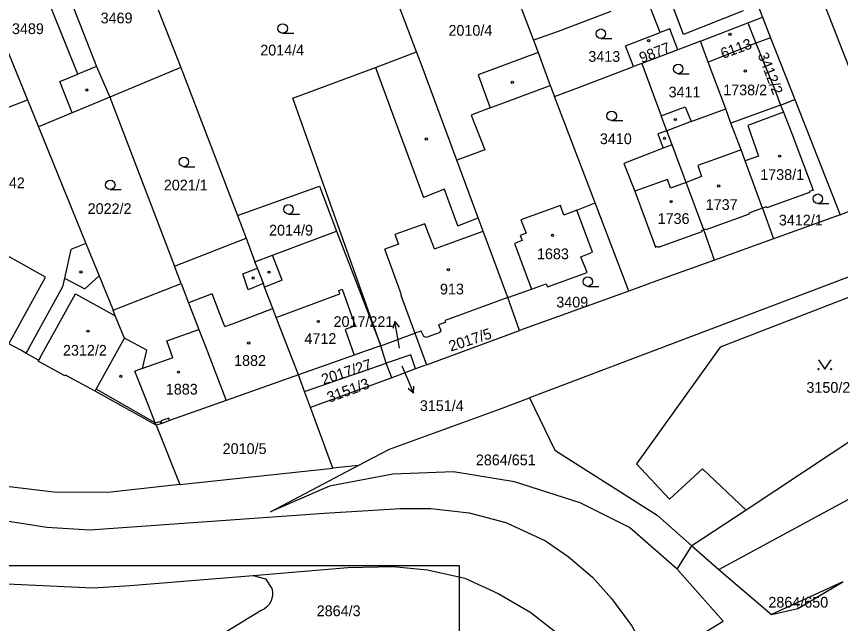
# Model space of a CAD drawing. Extents: x -564952 to -564307, y -1202373 to -1201847.
# Drawn here: x -564610.5 to -564479.9, y -1201998.2 to -1201901.9 of the extents above; entities that cross this region are included whole.
import ezdxf

# ---------------------------------------------------------------- set-up
doc = ezdxf.new("R2010")
doc.units = 0
for name, color, linetype in [('Hranice parcel', 7, 'Continuous'), ('Parcelní čísla', 7, 'Continuous'), ('Pop  PČ popisy', 7, 'Continuous'), ('Vnitřní kresba', 7, 'Continuous'), ('Vrstva 63', 7, 'Continuous'), ('Značky budov', 7, 'Continuous'), ('Značky kultur', 7, 'Continuous')]:
    doc.layers.add(name, color=color, linetype=linetype)

msp = doc.modelspace()

# ---------------------------------------------------------------- linework, layer by layer
at = {"layer": 'Hranice parcel'}
for p, q in [((-564547.1, -1201907.51), (-564552.42, -1201893.39)), ((-564495.75, -1201893.11), (-564492.24, -1201902.04)), ((-564616.36, -1201896.58), (-564608.79, -1201915.11)), ((-564531.91, -1201896.79), (-564528.57, -1201905.64)), ((-564478.1, -1201911.04), (-564483.28, -1201897.71)), ((-564508.48, -1201904.46), (-564510.58, -1201899.01)), ((-564588.08, -1201900.86), (-564584.48, -1201910.01)), ((-564516.27, -1201901.14), (-564524.64, -1201904.29)), ((-564492.24, -1201902.04), (-564491, -1201905.29)), ((-564524.64, -1201904.29), (-564528.57, -1201905.64)), ((-564513.97, -1201906.54), (-564508.48, -1201904.46)), ((-564506.95, -1201903.88), (-564508.48, -1201904.46)), ((-564505.69, -1201907.18), (-564506.95, -1201903.88)), ((-564528.57, -1201905.64), (-564527.83, -1201907.62)), ((-564502.08, -1201905.8), (-564505.69, -1201907.18)), ((-564500.85, -1201909.16), (-564502.08, -1201905.8)), ((-564491, -1201905.29), (-564493.31, -1201906.15)), ((-564491, -1201905.29), (-564487.11, -1201915.1)), ((-564512.71, -1201909.86), (-564513.97, -1201906.54)), ((-564493.31, -1201906.15), (-564500.85, -1201909.16)), ((-564493.31, -1201906.15), (-564490.23, -1201913.66)), ((-564505.69, -1201907.18), (-564511.4, -1201909.36)), ((-564511.4, -1201909.36), (-564512.71, -1201909.86)), ((-564511.4, -1201909.36), (-564508.3, -1201917.67)), ((-564498.06, -1201916.56), (-564500.85, -1201909.16)), ((-564584.48, -1201910.01), (-564595.73, -1201914.71)), ((-564584.48, -1201910.01), (-564575.5, -1201933.47)), ((-564595.73, -1201914.71), (-564601.71, -1201917.21)), ((-564595.73, -1201914.71), (-564585.46, -1201941.52)), ((-564518.79, -1201931.46), (-564525.23, -1201914.6)), ((-564490.23, -1201913.66), (-564489.4, -1201915.99)), ((-564617.51, -1201918.49), (-564608.79, -1201915.11)), ((-564608.79, -1201915.11), (-564607.03, -1201919.43)), ((-564489.4, -1201915.99), (-564497.27, -1201918.81)), ((-564489.4, -1201915.99), (-564487.11, -1201915.1)), ((-564487.11, -1201915.1), (-564479.94, -1201933.37)), ((-564601.71, -1201917.21), (-564607.03, -1201919.43)), ((-564497.27, -1201918.81), (-564498.06, -1201916.56)), ((-564507.42, -1201920.02), (-564508.3, -1201917.67)), ((-564607.03, -1201919.43), (-564599.52, -1201937.9)), ((-564492.22, -1201932.31), (-564494.98, -1201924.79)), ((-564479.94, -1201933.37), (-564470.88, -1201929.59)), ((-564513.43, -1201945.49), (-564518.79, -1201931.46)), ((-564492.22, -1201932.31), (-564490.5, -1201937.16)), ((-564575.5, -1201933.47), (-564574.13, -1201937.05)), ((-564479.94, -1201933.37), (-564490.5, -1201937.16)), ((-564499.88, -1201940.55), (-564501.55, -1201935.74)), ((-564585.46, -1201941.52), (-564574.13, -1201937.05)), ((-564574.13, -1201937.05), (-564572.71, -1201940.81)), ((-564490.5, -1201937.16), (-564499.88, -1201940.55)), ((-564599.52, -1201937.9), (-564601.88, -1201938.86)), ((-564584.42, -1201944.24), (-564585.46, -1201941.52)), ((-564595.21, -1201948.49), (-564584.42, -1201944.24)), ((-564513.43, -1201945.49), (-564530.75, -1201951.7)), ((-564530.75, -1201951.7), (-564532.64, -1201946.48)), ((-564594.85, -1201949.38), (-564595.21, -1201948.49)), ((-564449.87, -1201950.46), (-564494.86, -1201980.19)), ((-564552.78, -1201954.12), (-564547.35, -1201952.15)), ((-564547.35, -1201952.15), (-564545.5, -1201957.14)), ((-564545.5, -1201957.14), (-564530.75, -1201951.7)), ((-564551.91, -1201956.9), (-564552.78, -1201954.12)), ((-564564.86, -1201961.36), (-564551.91, -1201956.9)), ((-564551.03, -1201959.23), (-564551.91, -1201956.9)), ((-564547.25, -1201957.78), (-564551.03, -1201959.23)), ((-564545.5, -1201957.14), (-564547.25, -1201957.78)), ((-564565.82, -1201958.76), (-564577.26, -1201962.81)), ((-564564.86, -1201961.36), (-564565.82, -1201958.76)), ((-564551.03, -1201959.23), (-564563.92, -1201963.93)), ((-564499.17, -1201989.59), (-564443.23, -1201959.33)), ((-564588.36, -1201966.75), (-564598.04, -1201961.33)), ((-564563.92, -1201963.93), (-564564.86, -1201961.36)), ((-564560.38, -1201973.55), (-564563.92, -1201963.93)), ((-564588.36, -1201966.75), (-564584.64, -1201976.16)), ((-564556.34, -1201973.12), (-564551.4, -1201970.51)), ((-564584.64, -1201976.16), (-564560.38, -1201973.55)), ((-564570.25, -1201980.49), (-564556.34, -1201973.12)), ((-564556.34, -1201973.12), (-564560.38, -1201973.55)), ((-564584.64, -1201976.16), (-564596.05, -1201977.38)), ((-564494.86, -1201980.19), (-564503.43, -1201985.86)), ((-564505.77, -1201989.55), (-564503.43, -1201985.86)), ((-564503.43, -1201985.86), (-564499.17, -1201989.59)), ((-564499.17, -1201989.59), (-564490.82, -1201996.75)), ((-564479.51, -1201991.57), (-564490.82, -1201996.75))]:
    msp.add_line(p, q, dxfattribs=at)
for points in [[(-564328.21, -1201853.59), (-564368.6, -1201879.82), (-564418.44, -1201912.36), (-564448.23, -1201931.71), (-564529.16, -1201962.4)], [(-564605.73, -1201889.7), (-564597.83, -1201909.85), (-564595.73, -1201914.71)], [(-564601.71, -1201917.21), (-564603.64, -1201912.23), (-564600.77, -1201911.06), (-564609.03, -1201890.5), (-564617.5, -1201893.79)], [(-564502.08, -1201905.8), (-564494.55, -1201902.93), (-564492.24, -1201902.04)], [(-564552.78, -1201954.12), (-564566.71, -1201914.88), (-564553.62, -1201910), (-564547.1, -1201907.51)], [(-564540.7, -1201924.68), (-564546.38, -1201909.43), (-564547.1, -1201907.51)], [(-564527.83, -1201907.62), (-564537.35, -1201911.15), (-564535.4, -1201916.41), (-564538.41, -1201917.54), (-564536.27, -1201923.04), (-564540.7, -1201924.68)], [(-564527.83, -1201907.62), (-564525.9, -1201912.85), (-564525.23, -1201914.6)], [(-564525.23, -1201914.6), (-564521.26, -1201913.13), (-564512.71, -1201909.86)], [(-564508.3, -1201917.67), (-564504.49, -1201916.22), (-564503.58, -1201918.58), (-564498.06, -1201916.56)], [(-564489.4, -1201915.99), (-564488.94, -1201917.09), (-564487.61, -1201920.46), (-564484.22, -1201929.43), (-564484.85, -1201929.66), (-564484.8, -1201929.8), (-564491.58, -1201932.24), (-564491.63, -1201932.1), (-564492.22, -1201932.31)], [(-564494.98, -1201924.79), (-564495.65, -1201923.04), (-564497.27, -1201918.81)], [(-564507.42, -1201920.02), (-564508.83, -1201920.54), (-564507.97, -1201922.8), (-564514.25, -1201925.2), (-564512.5, -1201929.62), (-564509.2, -1201938.48), (-564508.78, -1201938.33), (-564508.73, -1201938.47), (-564501.79, -1201935.99), (-564501.84, -1201935.84), (-564501.55, -1201935.74)], [(-564501.55, -1201935.74), (-564504.36, -1201928.22), (-564506.58, -1201922.27), (-564507.42, -1201920.02)], [(-564611.74, -1201953.8), (-564605.93, -1201943.27), (-564620.21, -1201935.26), (-564625.61, -1201921.62)], [(-564532.64, -1201946.48), (-564536.54, -1201935.93), (-564537.32, -1201933.82), (-564540.7, -1201924.68)], [(-564575.5, -1201933.47), (-564562.5, -1201928.84), (-564559.77, -1201935.95)], [(-564532.64, -1201946.48), (-564528.88, -1201945.17), (-564526.56, -1201944.3), (-564526.33, -1201944.79), (-564520.04, -1201942.52), (-564521.03, -1201940.02), (-564519.2, -1201939.31), (-564521.68, -1201932.6), (-564518.79, -1201931.46)], [(-564572.71, -1201940.81), (-564569.93, -1201939.76), (-564559.77, -1201935.95)], [(-564559.77, -1201935.95), (-564556.55, -1201944.31), (-564552.78, -1201954.12)], [(-564599.52, -1201937.9), (-564597.42, -1201943.05), (-564595.21, -1201948.49)], [(-564601.88, -1201938.86), (-564602.91, -1201943.41), (-564603.23, -1201944.81), (-564608.78, -1201954.86), (-564609.02, -1201955.3)], [(-564565.82, -1201958.76), (-564569.35, -1201949.64), (-564569.88, -1201948.24), (-564571.18, -1201944.82), (-564571.38, -1201944.24), (-564572.31, -1201941.81), (-564572.71, -1201940.81)], [(-564499.88, -1201940.55), (-564509.16, -1201943.91), (-564513.43, -1201945.49)], [(-564461.46, -1201941.96), (-564463.36, -1201940.57), (-564498.95, -1201954.33), (-564512.2, -1201972.88), (-564507.01, -1201978.45), (-564501.74, -1201973.64), (-564494.86, -1201980.19)], [(-564584.42, -1201944.24), (-564583.26, -1201947.33), (-564581.6, -1201951.56), (-564580.56, -1201954.26), (-564577.26, -1201962.81)], [(-564596.05, -1201977.38), (-564604.58, -1201977.37), (-564614.37, -1201976.21), (-564623.15, -1201973.61), (-564632.26, -1201969.32), (-564640.22, -1201963.11), (-564646.58, -1201956.32), (-564653.95, -1201945.36)], [(-564532.64, -1201946.48), (-564542.57, -1201950.11), (-564542.56, -1201950.43), (-564543.59, -1201950.82), (-564543.24, -1201951.69), (-564543.5, -1201952.1), (-564545.56, -1201952.83), (-564545.96, -1201952.65), (-564546.36, -1201951.79), (-564547.35, -1201952.15)], [(-564598.04, -1201961.33), (-564597.87, -1201961.02), (-564593.4, -1201952.95), (-564594.85, -1201949.38)], [(-564609.02, -1201955.3), (-564609.82, -1201954.85), (-564611.74, -1201953.8)], [(-564552.78, -1201954.12), (-564555.39, -1201955.05), (-564556.96, -1201955.61), (-564565.82, -1201958.76)], [(-564598.04, -1201961.33), (-564602.77, -1201958.77), (-564602.84, -1201958.9), (-564607.08, -1201956.55), (-564607.01, -1201956.41), (-564609.02, -1201955.3)], [(-564547.25, -1201957.78), (-564548.02, -1201955.55), (-564551.91, -1201956.9)], [(-564577.26, -1201962.81), (-564586.11, -1201965.95), (-564586.24, -1201966), (-564587.5, -1201966.44), (-564587.66, -1201966.5), (-564588.36, -1201966.75)], [(-564551.4, -1201970.51), (-564533.92, -1201964.19), (-564529.16, -1201962.4)], [(-564529.16, -1201962.4), (-564525.19, -1201970.67), (-564508.96, -1201981), (-564503.43, -1201985.86)], [(-564505.77, -1201989.55), (-564513.32, -1201982.96), (-564521.17, -1201979.06), (-564531.54, -1201975.72), (-564541.26, -1201974.14), (-564550.84, -1201974.47), (-564560.9, -1201976.42), (-564570.25, -1201980.49)], [(-564623.41, -1201978.76), (-564612.8, -1201981.8), (-564605.69, -1201982.88)], [(-564605.69, -1201982.88), (-564598.88, -1201983.3), (-564561.75, -1201980.66), (-564553.92, -1201980.18), (-564549.62, -1201979.94), (-564544.81, -1201979.95), (-564538.75, -1201980.64), (-564532.96, -1201982.16), (-564526.67, -1201985.07), (-564523.04, -1201987.55), (-564519.22, -1201990.84), (-564516.18, -1201994.23), (-564513.04, -1201998.5), (-564509.57, -1202004.53)], [(-564640.45, -1201981.26), (-564637.68, -1201983.33), (-564632.21, -1201986.09), (-564621.75, -1201989.88), (-564611.99, -1201991.88), (-564598.44, -1201992.53), (-564592.52, -1201992.17), (-564572.99, -1201990.58)], [(-564572.99, -1201990.58), (-564557.98, -1201989.28), (-564550.78, -1201989.16), (-564545.37, -1201989.69), (-564539.44, -1201991.01), (-564534.17, -1201993.43), (-564528.95, -1201996.43), (-564523.84, -1202000.46), (-564519.2, -1202005.26)], [(-564572.99, -1201990.58), (-564571.06, -1201991.11), (-564570.05, -1201992.61)], [(-564509.57, -1202004.53), (-564498.5, -1201997.83), (-564505.77, -1201989.55)], [(-564490.82, -1201996.75), (-564486.65, -1201995.79), (-564479.51, -1201991.57)], [(-564570.05, -1201992.61), (-564569.94, -1201993.14), (-564569.94, -1201993.68), (-564570.03, -1201994.21), (-564570.2, -1201994.68), (-564570.47, -1201995.14), (-564570.83, -1201995.55), (-564571.25, -1201995.89), (-564571.73, -1201996.14)], [(-564571.73, -1201996.14), (-564596.1, -1202011.05), (-564599.43, -1202013.53), (-564603.54, -1202017.13)]]:
    msp.add_lwpolyline(points, dxfattribs=at)
at = {"layer": 'Pop  PČ popisy'}
for p, q in [((-564550.53, -1201950.3), (-564550.85, -1201951.38)), ((-564550.01, -1201953.26), (-564550.53, -1201950.3)), ((-564550.53, -1201950.3), (-564549.86, -1201951.2)), ((-564549.8, -1201954.52), (-564550.01, -1201953.26)), ((-564549.44, -1201957.31), (-564548.76, -1201958.89)), ((-564548.76, -1201958.89), (-564547.59, -1201961.65)), ((-564547.59, -1201961.65), (-564547.52, -1201960.53)), ((-564547.59, -1201961.65), (-564548.44, -1201960.93))]:
    msp.add_line(p, q, dxfattribs=at)
at = {"layer": 'Vnitřní kresba'}
for p, q in [((-564504.75, -1201904.79), (-564507.38, -1201897.8)), ((-564495.3, -1201901.02), (-564504.75, -1201904.79)), ((-564494.55, -1201902.93), (-564493.31, -1201906.15)), ((-564597.83, -1201909.85), (-564600.77, -1201911.06)), ((-564553.62, -1201910), (-564550.91, -1201917.34)), ((-564535.4, -1201916.41), (-564525.9, -1201912.85)), ((-564550.91, -1201917.34), (-564546.01, -1201930.61)), ((-564488.94, -1201917.09), (-564494.56, -1201919.18)), ((-564503.58, -1201918.58), (-564507.42, -1201920.02)), ((-564494.56, -1201919.18), (-564492.87, -1201924.04)), ((-564506.58, -1201922.27), (-564507.97, -1201922.8)), ((-564497.8, -1201923.83), (-564502.5, -1201925.53)), ((-564495.65, -1201923.04), (-564497.8, -1201923.83)), ((-564492.87, -1201924.04), (-564494.98, -1201924.79)), ((-564502.5, -1201925.53), (-564501.94, -1201927.3)), ((-564507.28, -1201927.76), (-564512.5, -1201929.62)), ((-564506.81, -1201929.14), (-564507.28, -1201927.76)), ((-564501.94, -1201927.3), (-564504.36, -1201928.22)), ((-564542.64, -1201929.32), (-564546.01, -1201930.61)), ((-564542.27, -1201930.34), (-564542.64, -1201929.32)), ((-564504.36, -1201928.22), (-564506.81, -1201929.14)), ((-564540.55, -1201935.11), (-564542.27, -1201930.34)), ((-564524.27, -1201931.91), (-564530.56, -1201934.15)), ((-564523.76, -1201933.42), (-564524.27, -1201931.91)), ((-564521.68, -1201932.6), (-564523.76, -1201933.42)), ((-564494.35, -1201933.25), (-564501.21, -1201935.77)), ((-564493.99, -1201932.96), (-564494.4, -1201933.11)), ((-564494.4, -1201933.11), (-564494.35, -1201933.25)), ((-564492.22, -1201932.31), (-564493.99, -1201932.96)), ((-564540.55, -1201935.11), (-564537.32, -1201933.82)), ((-564530.56, -1201934.15), (-564529.74, -1201936.28)), ((-564545.78, -1201934.77), (-564550.51, -1201936.49)), ((-564545.19, -1201936.31), (-564545.78, -1201934.77)), ((-564501.26, -1201935.63), (-564501.55, -1201935.74)), ((-564501.21, -1201935.77), (-564501.26, -1201935.63)), ((-564550.51, -1201936.49), (-564549.95, -1201938.04)), ((-564544.25, -1201938.78), (-564545.19, -1201936.31)), ((-564544.25, -1201938.78), (-564536.54, -1201935.93)), ((-564529.74, -1201936.28), (-564530.67, -1201936.63)), ((-564530.67, -1201936.63), (-564530.36, -1201937.46)), ((-564549.95, -1201938.04), (-564552.1, -1201938.82)), ((-564530.36, -1201937.46), (-564531.57, -1201937.91)), ((-564531.57, -1201937.91), (-564528.88, -1201945.17)), ((-564568.38, -1201943.75), (-564569.93, -1201939.76)), ((-564549.46, -1201946.06), (-564552.1, -1201938.82)), ((-564574.65, -1201942.71), (-564572.31, -1201941.81)), ((-564602.91, -1201943.41), (-564599.68, -1201945.1)), ((-564599.68, -1201945.1), (-564597.42, -1201943.05)), ((-564573.79, -1201945.25), (-564574.65, -1201942.71)), ((-564571.52, -1201944.3), (-564573.79, -1201945.25)), ((-564571.38, -1201944.24), (-564571.52, -1201944.3)), ((-564568.38, -1201943.75), (-564571.18, -1201944.82)), ((-564606.76, -1201955.98), (-564601.19, -1201945.92)), ((-564601.19, -1201945.92), (-564594.85, -1201949.38)), ((-564579.48, -1201945.88), (-564583.26, -1201947.33)), ((-564578, -1201949.74), (-564579.48, -1201945.88)), ((-564569.35, -1201949.64), (-564559.23, -1201945.91)), ((-564559.43, -1201945.37), (-564558.91, -1201945.18)), ((-564559.23, -1201945.91), (-564559.43, -1201945.37)), ((-564558.91, -1201945.18), (-564556.84, -1201950.98)), ((-564549.58, -1201946.12), (-564549.46, -1201946.06)), ((-564549.58, -1201946.12), (-564547.35, -1201952.15)), ((-564576.29, -1201950.65), (-564570.02, -1201948.29)), ((-564570.02, -1201948.29), (-564569.88, -1201948.24)), ((-564577.48, -1201951.1), (-564578, -1201949.74)), ((-564577.48, -1201951.1), (-564576.29, -1201950.65)), ((-564556.84, -1201950.98), (-564558.41, -1201951.54)), ((-564558.41, -1201951.54), (-564556.96, -1201955.61)), ((-564586.66, -1201953.34), (-564581.6, -1201951.56)), ((-564589.85, -1201954.85), (-564593.4, -1201952.95)), ((-564585.72, -1201956.05), (-564586.66, -1201953.34)), ((-564590.56, -1201957.73), (-564589.85, -1201954.85)), ((-564606.76, -1201955.98), (-564607.01, -1201956.41)), ((-564585.72, -1201956.05), (-564590.56, -1201957.73)), ((-564590.56, -1201957.73), (-564591.76, -1201958.15)), ((-564589.61, -1201963.6), (-564591.76, -1201958.15)), ((-564588.51, -1201966.38), (-564597.87, -1201961.02)), ((-564588.51, -1201966.38), (-564589.61, -1201963.6)), ((-564586.39, -1201965.59), (-564587.64, -1201966.06)), ((-564586.24, -1201966), (-564586.39, -1201965.59)), ((-564588.51, -1201966.38), (-564587.8, -1201966.12)), ((-564588.36, -1201966.75), (-564588.51, -1201966.38)), ((-564587.8, -1201966.12), (-564587.66, -1201966.5)), ((-564587.64, -1201966.06), (-564587.5, -1201966.44))]:
    msp.add_line(p, q, dxfattribs=at)
at = {"layer": 'Vrstva 63'}
msp.add_lwpolyline([(-564540.34, -1202137.49), (-564645.34, -1202137.49), (-564645.34, -1201988.99), (-564540.34, -1201988.99)], close=True, dxfattribs=at)
at = {"layer": 'Značky budov'}
for centre in [(-564510.28, -1201905.74), (-564497.4, -1201904.73), (-564494.97, -1201910.54), (-564531.91, -1201912.34), (-564599.37, -1201913.56), (-564506.07, -1201918.25), (-564545.55, -1201921.33), (-564507.79, -1201921.24), (-564489.54, -1201924.07), (-564499.21, -1201928.8), (-564506.72, -1201931.26), (-564525.54, -1201936.62), (-564600.28, -1201942.42), (-564570.5, -1201942.46), (-564542.04, -1201942.07), (-564572.99, -1201943.39), (-564562.65, -1201950.28), (-564599.19, -1201951.82), (-564573.7, -1201953.68), (-564593.97, -1201958.97), (-564584.83, -1201958.31)]:
    msp.add_circle(centre, 0.175, dxfattribs=at)
at = {"layer": 'Značky kultur'}
for p, q in [((-564568.32, -1201904.55), (-564566.57, -1201904.55)), ((-564517.87, -1201905.39), (-564516.12, -1201905.39)), ((-564505.61, -1201910.98), (-564503.86, -1201910.98)), ((-564516.16, -1201918.43), (-564514.41, -1201918.43)), ((-564583.98, -1201925.73), (-564582.23, -1201925.73)), ((-564595.65, -1201929.36), (-564593.9, -1201929.36)), ((-564483.47, -1201931.56), (-564481.72, -1201931.56)), ((-564567.39, -1201933.24), (-564565.64, -1201933.24)), ((-564519.94, -1201944.71), (-564518.19, -1201944.71))]:
    msp.add_line(p, q, dxfattribs=at)
msp.add_lwpolyline([(-564483.36, -1201956.34), (-564482.36, -1201957.84), (-564481.36, -1201956.34)], dxfattribs=at)
for centre, radius in [((-564568.32, -1201903.8), 0.75), ((-564517.87, -1201904.64), 0.75), ((-564505.61, -1201910.23), 0.75), ((-564516.16, -1201917.68), 0.75), ((-564583.98, -1201924.98), 0.75), ((-564595.65, -1201928.61), 0.75), ((-564483.47, -1201930.81), 0.75), ((-564567.39, -1201932.49), 0.75), ((-564519.94, -1201943.96), 0.75), ((-564483.36, -1201957.84), 0.1), ((-564481.36, -1201957.84), 0.1)]:
    msp.add_circle(centre, radius, dxfattribs=at)

# ---------------------------------------------------------------- texts
at = {"layer": 'Parcelní čísla'}
for s, p in [('3469', (-564597.18, -1201903)), ('3489', (-564611.24, -1201904.7)), ('2010/4', (-564542.03, -1201904.96)), ('2014/4', (-564571.87, -1201908.09)), ('3413', (-564519.86, -1201909.1)), ('3411', (-564507.13, -1201914.74)), ('1738/2', (-564498.47, -1201914.41)), ('3410', (-564518.03, -1201922.15)), ('1738/1', (-564492.6, -1201927.83)), ('10542', (-564615.52, -1201929.14)), ('2021/1', (-564587.16, -1201929.49)), ('2022/2', (-564599.24, -1201933.23)), ('1737', (-564501.25, -1201932.59)), ('1736', (-564508.87, -1201934.81)), ('3412/1', (-564489.65, -1201935.05)), ('2014/9', (-564570.47, -1201936.65)), ('1683', (-564528, -1201940.4)), ('913', (-564543.38, -1201945.99)), ('3409', (-564524.94, -1201948.06)), ('2017/221', (-564560.25, -1201951.15)), ('4712', (-564564.86, -1201953.84)), ('2312/2', (-564603.15, -1201955.7)), ('1882', (-564576.02, -1201957.32)), ('1883', (-564586.84, -1201961.87)), ('3150/2', (-564485.28, -1201961.59)), ('3151/4', (-564546.57, -1201964.48)), ('2010/5', (-564577.83, -1201971.3)), ('2864/651', (-564537.69, -1201973.08)), ('2864/650', (-564491.31, -1201995.66)), ('2864/3', (-564562.92, -1201997.02))]:
    msp.add_text(s, height=1.7, dxfattribs=at).set_placement(p)
for s, rotation, p in [('6113', 20, (-564498.52, -1201908.65)), ('9877', 21, (-564511.39, -1201909.33)), ('3412/2', 291, (-564493.03, -1201907.99)), ('2017/5', 18, (-564541.65, -1201955.06)), ('2017/27', 18, (-564561.85, -1201960.34)), ('3151/3', 20, (-564560.93, -1201963.18))]:
    msp.add_text(s, height=1.7, rotation=rotation, dxfattribs=at).set_placement(p)

doc.saveas('drawing.dxf')
